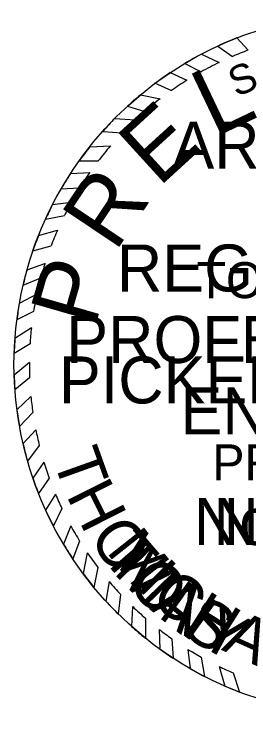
# Model space of a CAD drawing. Extents: x 1366406 to 1373462, y 376856 to 381998.
# Drawn here: x 1370682.3 to 1370744.8, y 379288.4 to 379474.9 of the extents above; entities that cross this region are included whole.
import ezdxf

# ---------------------------------------------------------------- set-up
doc = ezdxf.new("R2010")
doc.units = 0
for name, color, linetype in [('STAMP_PE_CRAFTON', 7, 'Continuous'), ('STAMP_PE_FOSTER', 7, 'Continuous'), ('STAMP_PE_SEAL-INFO', 7, 'Continuous'), ('STAMP_PE_TAEGTMEYER', 7, 'Continuous'), ('STAMP_PE_TXT', 7, 'Continuous'), ('STAMP_PRELIMINARY', 7, 'Continuous')]:
    doc.layers.add(name, color=color, linetype=linetype)

msp = doc.modelspace()

# ---------------------------------------------------------------- linework, layer by layer
at = {"layer": 'STAMP_PE_SEAL-INFO'}
for p, q in [((1370741.61, 379468.5), (1370744.56, 379465.24)), ((1370741.61, 379468.5), (1370744.56, 379465.24)), ((1370736.53, 379466.34), (1370740.43, 379463.59)), ((1370736.53, 379466.34), (1370740.43, 379463.59)), ((1370732.22, 379464.22), (1370736.86, 379461.97)), ((1370732.22, 379464.22), (1370736.86, 379461.97)), ((1370727.74, 379461.72), (1370732.06, 379459.49)), ((1370727.74, 379461.72), (1370732.06, 379459.49)), ((1370723.87, 379459.28), (1370728.29, 379457.26)), ((1370723.87, 379459.28), (1370728.29, 379457.26)), ((1370719.67, 379456.61), (1370724.23, 379454.56)), ((1370719.67, 379456.61), (1370724.23, 379454.56)), ((1370715.9, 379453.34), (1370721.19, 379452.33)), ((1370715.9, 379453.34), (1370721.19, 379452.33)), ((1370712.46, 379450.34), (1370717.05, 379448.95)), ((1370712.46, 379450.34), (1370717.05, 379448.95)), ((1370709.11, 379447.1), (1370714.55, 379446.69)), ((1370709.11, 379447.1), (1370714.55, 379446.69)), ((1370705.88, 379443.66), (1370711.1, 379443.28)), ((1370705.88, 379443.66), (1370711.1, 379443.28)), ((1370702.43, 379439.55), (1370707.92, 379439.77)), ((1370702.43, 379439.55), (1370707.92, 379439.77)), ((1370699.64, 379435.85), (1370704.69, 379435.8)), ((1370699.64, 379435.85), (1370704.69, 379435.8)), ((1370697.3, 379432.41), (1370702.46, 379432.75)), ((1370697.3, 379432.41), (1370702.46, 379432.75)), ((1370694.84, 379428.4), (1370699.73, 379428.6)), ((1370694.84, 379428.4), (1370699.73, 379428.6)), ((1370692.53, 379424.17), (1370697.51, 379424.82)), ((1370692.53, 379424.17), (1370697.51, 379424.82)), ((1370690.65, 379420.28), (1370695.67, 379421.32)), ((1370690.65, 379420.28), (1370695.67, 379421.32)), ((1370688.81, 379415.95), (1370693.85, 379417.42)), ((1370688.81, 379415.95), (1370693.85, 379417.42)), ((1370687.31, 379411.89), (1370692.15, 379413.25)), ((1370687.31, 379411.89), (1370692.15, 379413.25)), ((1370685.74, 379406.86), (1370690.51, 379408.55)), ((1370685.74, 379406.86), (1370690.51, 379408.55)), ((1370684.69, 379402.79), (1370689.39, 379404.71)), ((1370684.69, 379402.79), (1370689.39, 379404.71)), ((1370688.34, 379400.32), (1370683.68, 379397.83)), ((1370688.34, 379400.32), (1370683.68, 379397.83)), ((1370687.48, 379395.74), (1370683.02, 379393.51)), ((1370687.48, 379395.74), (1370683.02, 379393.51)), ((1370686.89, 379391.38), (1370682.52, 379388.57)), ((1370686.89, 379391.38), (1370682.52, 379388.57)), ((1370686.53, 379387.13), (1370682.31, 379384.56)), ((1370686.53, 379387.13), (1370682.31, 379384.56)), ((1370686.36, 379382.2), (1370682.31, 379378.84)), ((1370686.36, 379382.2), (1370682.31, 379378.84)), ((1370686.43, 379378.13), (1370682.51, 379374.88)), ((1370686.43, 379378.13), (1370682.51, 379374.88)), ((1370686.76, 379373.17), (1370683.05, 379369.61)), ((1370686.76, 379373.17), (1370683.05, 379369.61)), ((1370687.28, 379368.88), (1370683.74, 379365.15)), ((1370687.28, 379368.88), (1370683.74, 379365.15)), ((1370688.06, 379364.29), (1370684.67, 379360.62)), ((1370688.06, 379364.29), (1370684.67, 379360.62)), ((1370689, 379360.1), (1370685.88, 379355.95)), ((1370689, 379360.1), (1370685.88, 379355.95)), ((1370690.24, 379355.63), (1370687.29, 379351.45)), ((1370690.24, 379355.63), (1370687.29, 379351.45)), ((1370691.65, 379351.4), (1370688.83, 379347.29)), ((1370691.65, 379351.4), (1370688.83, 379347.29)), ((1370693.31, 379347.14), (1370690.69, 379342.92)), ((1370693.31, 379347.14), (1370690.69, 379342.92)), ((1370695.03, 379343.3), (1370692.75, 379338.7)), ((1370695.03, 379343.3), (1370692.75, 379338.7)), ((1370697.37, 379338.72), (1370695.47, 379333.82)), ((1370697.37, 379338.72), (1370695.47, 379333.82)), ((1370699.73, 379334.69), (1370697.89, 379329.98)), ((1370699.73, 379334.69), (1370697.89, 379329.98)), ((1370701.76, 379331.57), (1370700.66, 379326.05)), ((1370701.76, 379331.57), (1370700.66, 379326.05)), ((1370704.56, 379327.66), (1370703.55, 379322.36)), ((1370704.56, 379327.66), (1370703.55, 379322.36)), ((1370707.6, 379323.89), (1370706.74, 379318.69)), ((1370707.6, 379323.89), (1370706.74, 379318.69)), ((1370710.63, 379320.51), (1370710.01, 379315.29)), ((1370710.63, 379320.51), (1370710.01, 379315.29)), ((1370713.85, 379317.26), (1370713.56, 379311.97)), ((1370713.85, 379317.26), (1370713.56, 379311.97)), ((1370717.3, 379314.13), (1370717.26, 379308.84)), ((1370717.3, 379314.13), (1370717.26, 379308.84)), ((1370720.9, 379311.19), (1370721.08, 379305.94)), ((1370720.9, 379311.19), (1370721.08, 379305.94)), ((1370724.28, 379308.69), (1370724.64, 379303.51)), ((1370724.28, 379308.69), (1370724.64, 379303.51)), ((1370728.55, 379305.87), (1370729.16, 379300.75)), ((1370728.55, 379305.87), (1370729.16, 379300.75)), ((1370732.06, 379303.81), (1370732.97, 379298.68)), ((1370732.06, 379303.81), (1370732.97, 379298.68)), ((1370736.87, 379301.32), (1370738.43, 379296.1)), ((1370736.87, 379301.32), (1370738.43, 379296.1)), ((1370740.59, 379299.63), (1370742.32, 379294.52)), ((1370740.59, 379299.63), (1370742.32, 379294.52))]:
    msp.add_line(p, q, dxfattribs=at)
for radius, start, end in [(93.23, 111.3124, 114.7026), (93.23, 111.3124, 114.7026), (89.13, 110.3086, 113.1659), (89.13, 110.3086, 113.1659), (93.23, 117.6544, 120.8099), (93.23, 117.6544, 120.8099), (89.13, 115.6869, 119.1583), (89.13, 115.6869, 119.1583), (93.23, 123.6199, 126.5906), (93.23, 123.6199, 126.5906), (89.13, 121.9746, 125.11), (89.13, 121.9746, 125.11), (93.23, 129.7326, 132.5376), (93.23, 129.7326, 132.5376), (89.13, 127.5297, 130.9683), (89.13, 127.5297, 130.9683), (93.23, 135.4021, 138.3031), (93.23, 135.4021, 138.3031), (89.13, 133.1331, 136.2562), (89.13, 133.1331, 136.2562), (93.23, 141.6056, 144.4486), (93.23, 141.6056, 144.4486), (89.13, 139.301, 142.5873), (89.13, 139.301, 142.5873), (93.23, 147.0072, 149.899), (93.23, 147.0072, 149.899), (89.13, 145.0197, 148.2104), (89.13, 145.0197, 148.2104), (93.23, 152.864, 155.5189), (93.23, 152.864, 155.5189), (89.13, 151.0315, 153.573), (89.13, 151.0315, 153.573), (89.13, 156.3402, 159.2319), (89.13, 156.3402, 159.2319), (93.23, 158.4077, 161.0701), (93.23, 158.4077, 161.0701), (93.23, 164.3068, 166.894), (93.23, 164.3068, 166.894), (89.13, 162.4331, 165.0013), (89.13, 162.4331, 165.0013), (89.13, 167.9048, 170.9039), (89.13, 167.9048, 170.9039), (93.23, 170.0003, 172.6878), (93.23, 170.0003, 172.6878), (89.13, 173.73, 176.4734), (89.13, 173.73, 176.4734), (93.23, 175.7409, 178.2066), (93.23, 175.7409, 178.2066), (89.13, 179.6454, 182.2633), (89.13, 179.6454, 182.2633), (93.23, 181.7251, 184.1626), (93.23, 181.7251, 184.1626), (89.13, 185.4539, 188.234), (89.13, 185.4539, 188.234), (93.23, 187.4204, 190.1927), (93.23, 187.4204, 190.1927), (89.13, 191.2274, 193.9858), (89.13, 191.2274, 193.9858), (93.23, 193.0369, 195.9973), (93.23, 193.0369, 195.9973), (89.13, 196.9675, 199.8353), (89.13, 196.9675, 199.8353), (93.23, 198.8967, 201.6281), (93.23, 198.8967, 201.6281), (89.13, 202.7761, 205.4791), (89.13, 202.7761, 205.4791), (93.23, 204.5479, 207.4328), (93.23, 204.5479, 207.4328), (89.13, 208.7883, 211.7934), (89.13, 208.7883, 211.7934), (93.23, 210.8636, 213.6571), (93.23, 210.8636, 213.6571), (89.13, 214.1838, 217.2747), (89.13, 214.1838, 217.2747), (93.23, 216.6115, 219.491), (93.23, 216.6115, 219.491), (89.13, 220.3909, 223.3056), (89.13, 220.3909, 223.3056), (93.23, 222.48, 225.3801), (93.23, 222.48, 225.3801), (89.13, 226.2494, 229.2407), (89.13, 226.2494, 229.2407), (93.23, 228.3665, 231.348), (93.23, 228.3665, 231.348), (89.13, 232.229, 234.9336), (89.13, 232.229, 234.9336), (93.23, 234.295, 236.9452), (93.23, 234.295, 236.9452), (89.13, 238.2223, 240.8353), (89.13, 238.2223, 240.8353), (93.23, 240.1977, 242.8613), (93.23, 240.1977, 242.8613), (89.13, 244.3204, 246.9486), (89.13, 244.3204, 246.9486), (93.23, 246.576, 249.1558), (93.23, 246.576, 249.1558)]:
    msp.add_arc((1370775.49, 379381.65), radius, start, end, dxfattribs=at)
at = {"layer": 'STAMP_PRELIMINARY'}
msp.add_circle((1370775.49, 379381.65), 93.23, dxfattribs=at)
msp.add_circle((1370775.49, 379381.65), 93.23, dxfattribs=at)

# ---------------------------------------------------------------- texts
at = {"layer": 'STAMP_PE_CRAFTON'}
msp.add_text('No. 12370', height=12.5, dxfattribs=at).set_placement((1370730.11, 379333.62))
msp.add_text('No. 12370', height=12.5, dxfattribs=at).set_placement((1370730.11, 379333.62))
for s, rotation, p in [('T', 310.7442, (1370705.15, 379330.62)), ('T', 310.7442, (1370705.15, 379330.62)), ('O', 317.6422, (1370711.82, 379322.51)), ('O', 317.6422, (1370711.82, 379322.51)), ('N', 324.4537, (1370720.28, 379314.66)), ('N', 324.4537, (1370720.28, 379314.66)), ('Y', 331.1686, (1370730.61, 379307.5)), ('Y', 331.1686, (1370730.61, 379307.5))]:
    msp.add_text(s, height=12.5, rotation=rotation, dxfattribs=at).set_placement(p)
at = {"layer": 'STAMP_PE_FOSTER'}
msp.add_text('No. 9402', height=12.5, dxfattribs=at).set_placement((1370735.35, 379333.62))
msp.add_text('No. 9402', height=12.5, dxfattribs=at).set_placement((1370735.35, 379333.62))
for s, rotation, p in [('M', 308.339, (1370706.65, 379331.87)), ('M', 308.339, (1370706.65, 379331.87)), ('I', 314.1842, (1370714.63, 379322.49)), ('I', 314.1842, (1370714.63, 379322.49)), ('C', 319.8733, (1370718.17, 379318.96)), ('C', 319.8733, (1370718.17, 379318.96)), ('H', 327.7235, (1370727.46, 379311.6)), ('H', 327.7235, (1370727.46, 379311.6)), ('A', 335.7276, (1370737.27, 379305.78)), ('A', 335.7276, (1370737.27, 379305.78))]:
    msp.add_text(s, height=12, rotation=rotation, dxfattribs=at).set_placement(p)
at = {"layer": 'STAMP_PE_TAEGTMEYER'}
for s, rotation, p in [('T', 289.646, (1370692.44, 379356.75)), ('T', 289.646, (1370692.44, 379356.75)), ('H', 296.7339, (1370696.03, 379346.9)), ('H', 296.7339, (1370696.03, 379346.9)), ('O', 303.7708, (1370701.96, 379335.82)), ('O', 303.7708, (1370701.96, 379335.82)), ('M', 314.2033, (1370708.51, 379326.31)), ('M', 314.2033, (1370708.51, 379326.31)), ('A', 321.0594, (1370718.13, 379316.67)), ('A', 321.0594, (1370718.13, 379316.67)), ('S', 327.8239, (1370726.39, 379310.23)), ('S', 327.8239, (1370726.39, 379310.23))]:
    msp.add_text(s, height=12.5, rotation=rotation, dxfattribs=at).set_placement(p)
msp.add_text('No. 19605', height=12.5, dxfattribs=at).set_placement((1370730.11, 379333.62))
msp.add_text('No. 19605', height=12.5, dxfattribs=at).set_placement((1370730.11, 379333.62))
at = {"layer": 'STAMP_PE_TXT'}
msp.add_text('S', height=7.81, rotation=23.5541, dxfattribs=at).set_placement((1370741.48, 379452.68))
msp.add_text('S', height=7.81, rotation=23.5541, dxfattribs=at).set_placement((1370741.48, 379452.68))
for s, p in [('ARKANSAS', (1370724.42, 379433.75)), ('ARKANSAS', (1370724.42, 379433.75)), ('REGISTERED', (1370709.66, 379401.06)), ('REGISTERED', (1370709.66, 379401.06)), ('PROFESSIONAL', (1370696.18, 379382.04)), ('PROFESSIONAL', (1370696.18, 379382.04)), ('ENGINEER', (1370726.58, 379363.03)), ('ENGINEER', (1370726.58, 379363.03))]:
    msp.add_text(s, height=12.5, dxfattribs=at).set_placement(p)
at = {"layer": 'STAMP_PRELIMINARY'}
for s, rotation, p in [('L', 25.513, (1370735.58, 379441.92)), ('L', 25.513, (1370735.58, 379441.92)), ('E', 42.3578, (1370720.75, 379428.61)), ('E', 42.3578, (1370720.75, 379428.61)), ('R', 56.2292, (1370709.2, 379411.29)), ('R', 56.2292, (1370709.2, 379411.29)), ('P', 73.913, (1370703.71, 379391.05)), ('P', 73.913, (1370703.71, 379391.05))]:
    msp.add_text(s, height=18, rotation=rotation, dxfattribs=at).set_placement(p)
for s, height, p in [('TO REVISION', 9.6, (1370730.85, 379399.29)), ('TO REVISION', 9.6, (1370730.85, 379399.29)), ('PICKERING FIRM', 12.5, (1370694.22, 379371.28)), ('PICKERING FIRM', 12.5, (1370694.22, 379371.28)), ('PRINT DATE', 9.6, (1370735.07, 379350.8)), ('PRINT DATE', 9.6, (1370735.07, 379350.8))]:
    msp.add_text(s, height=height, dxfattribs=at).set_placement(p)

doc.saveas('drawing.dxf')
